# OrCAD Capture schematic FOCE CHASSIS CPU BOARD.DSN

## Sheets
1 PIC: size C; title: FOCE Chassis CPU Board; rev: A
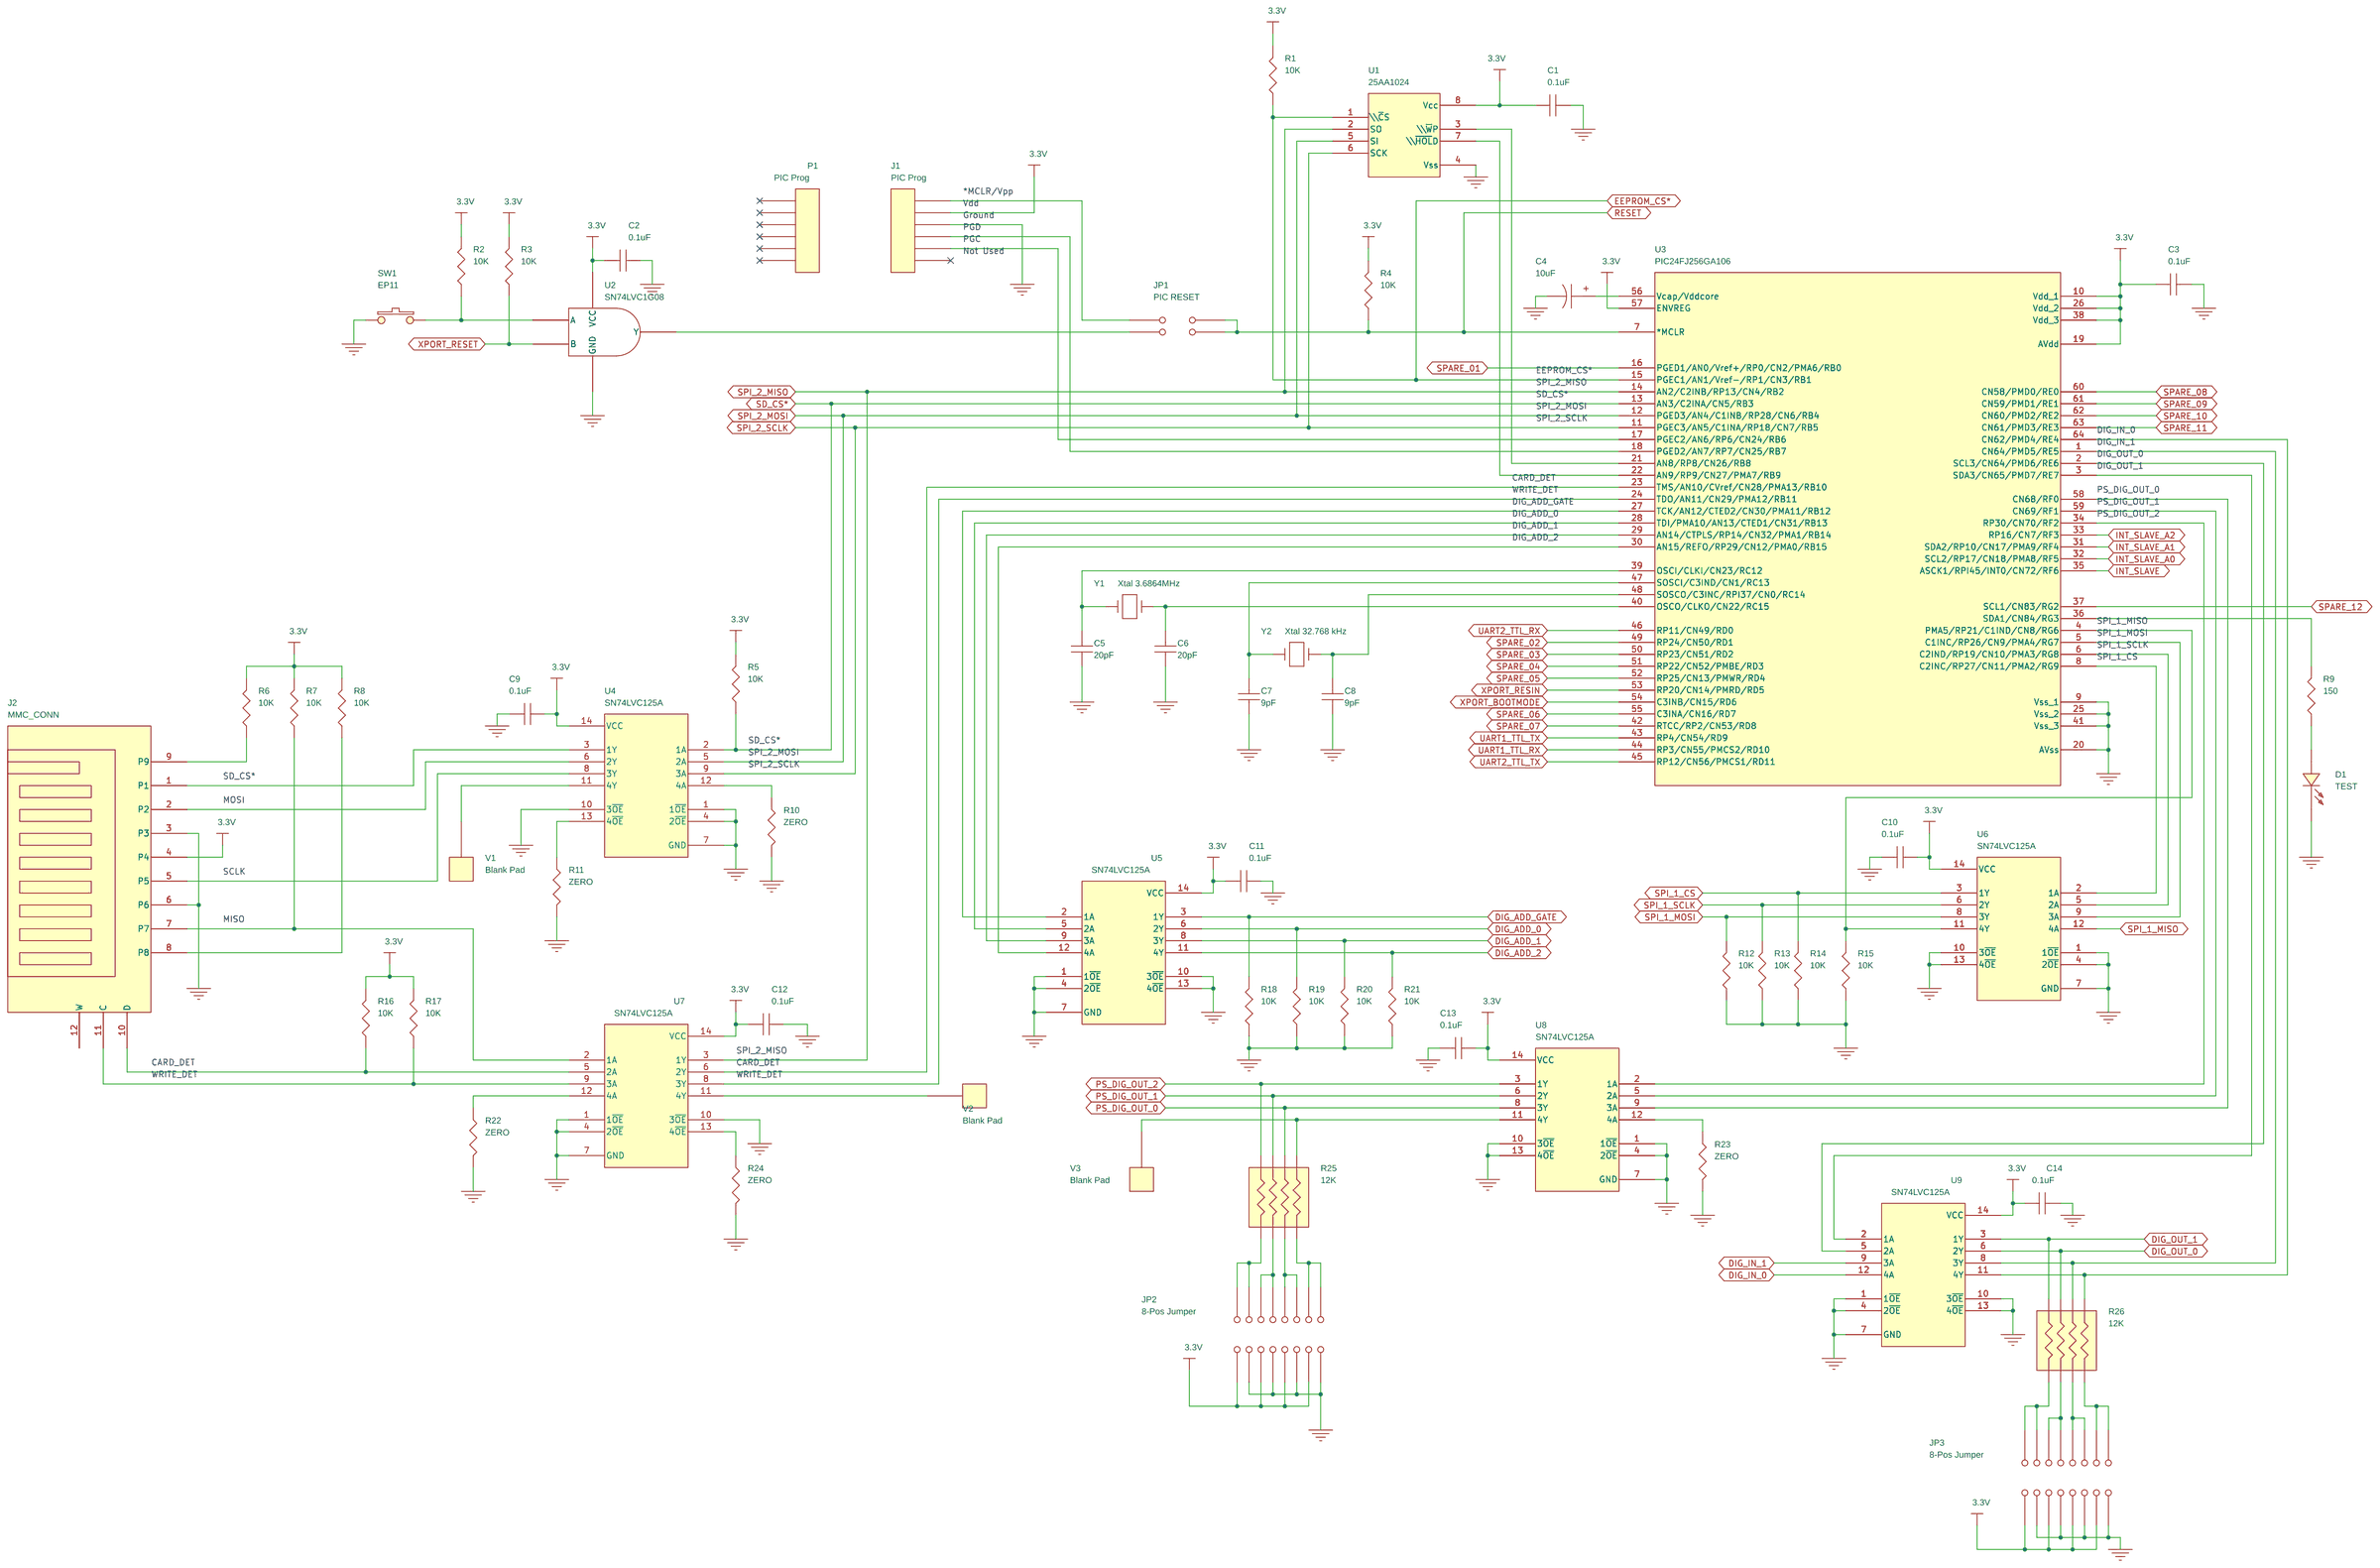
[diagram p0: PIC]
2 Backplance Connection: size C
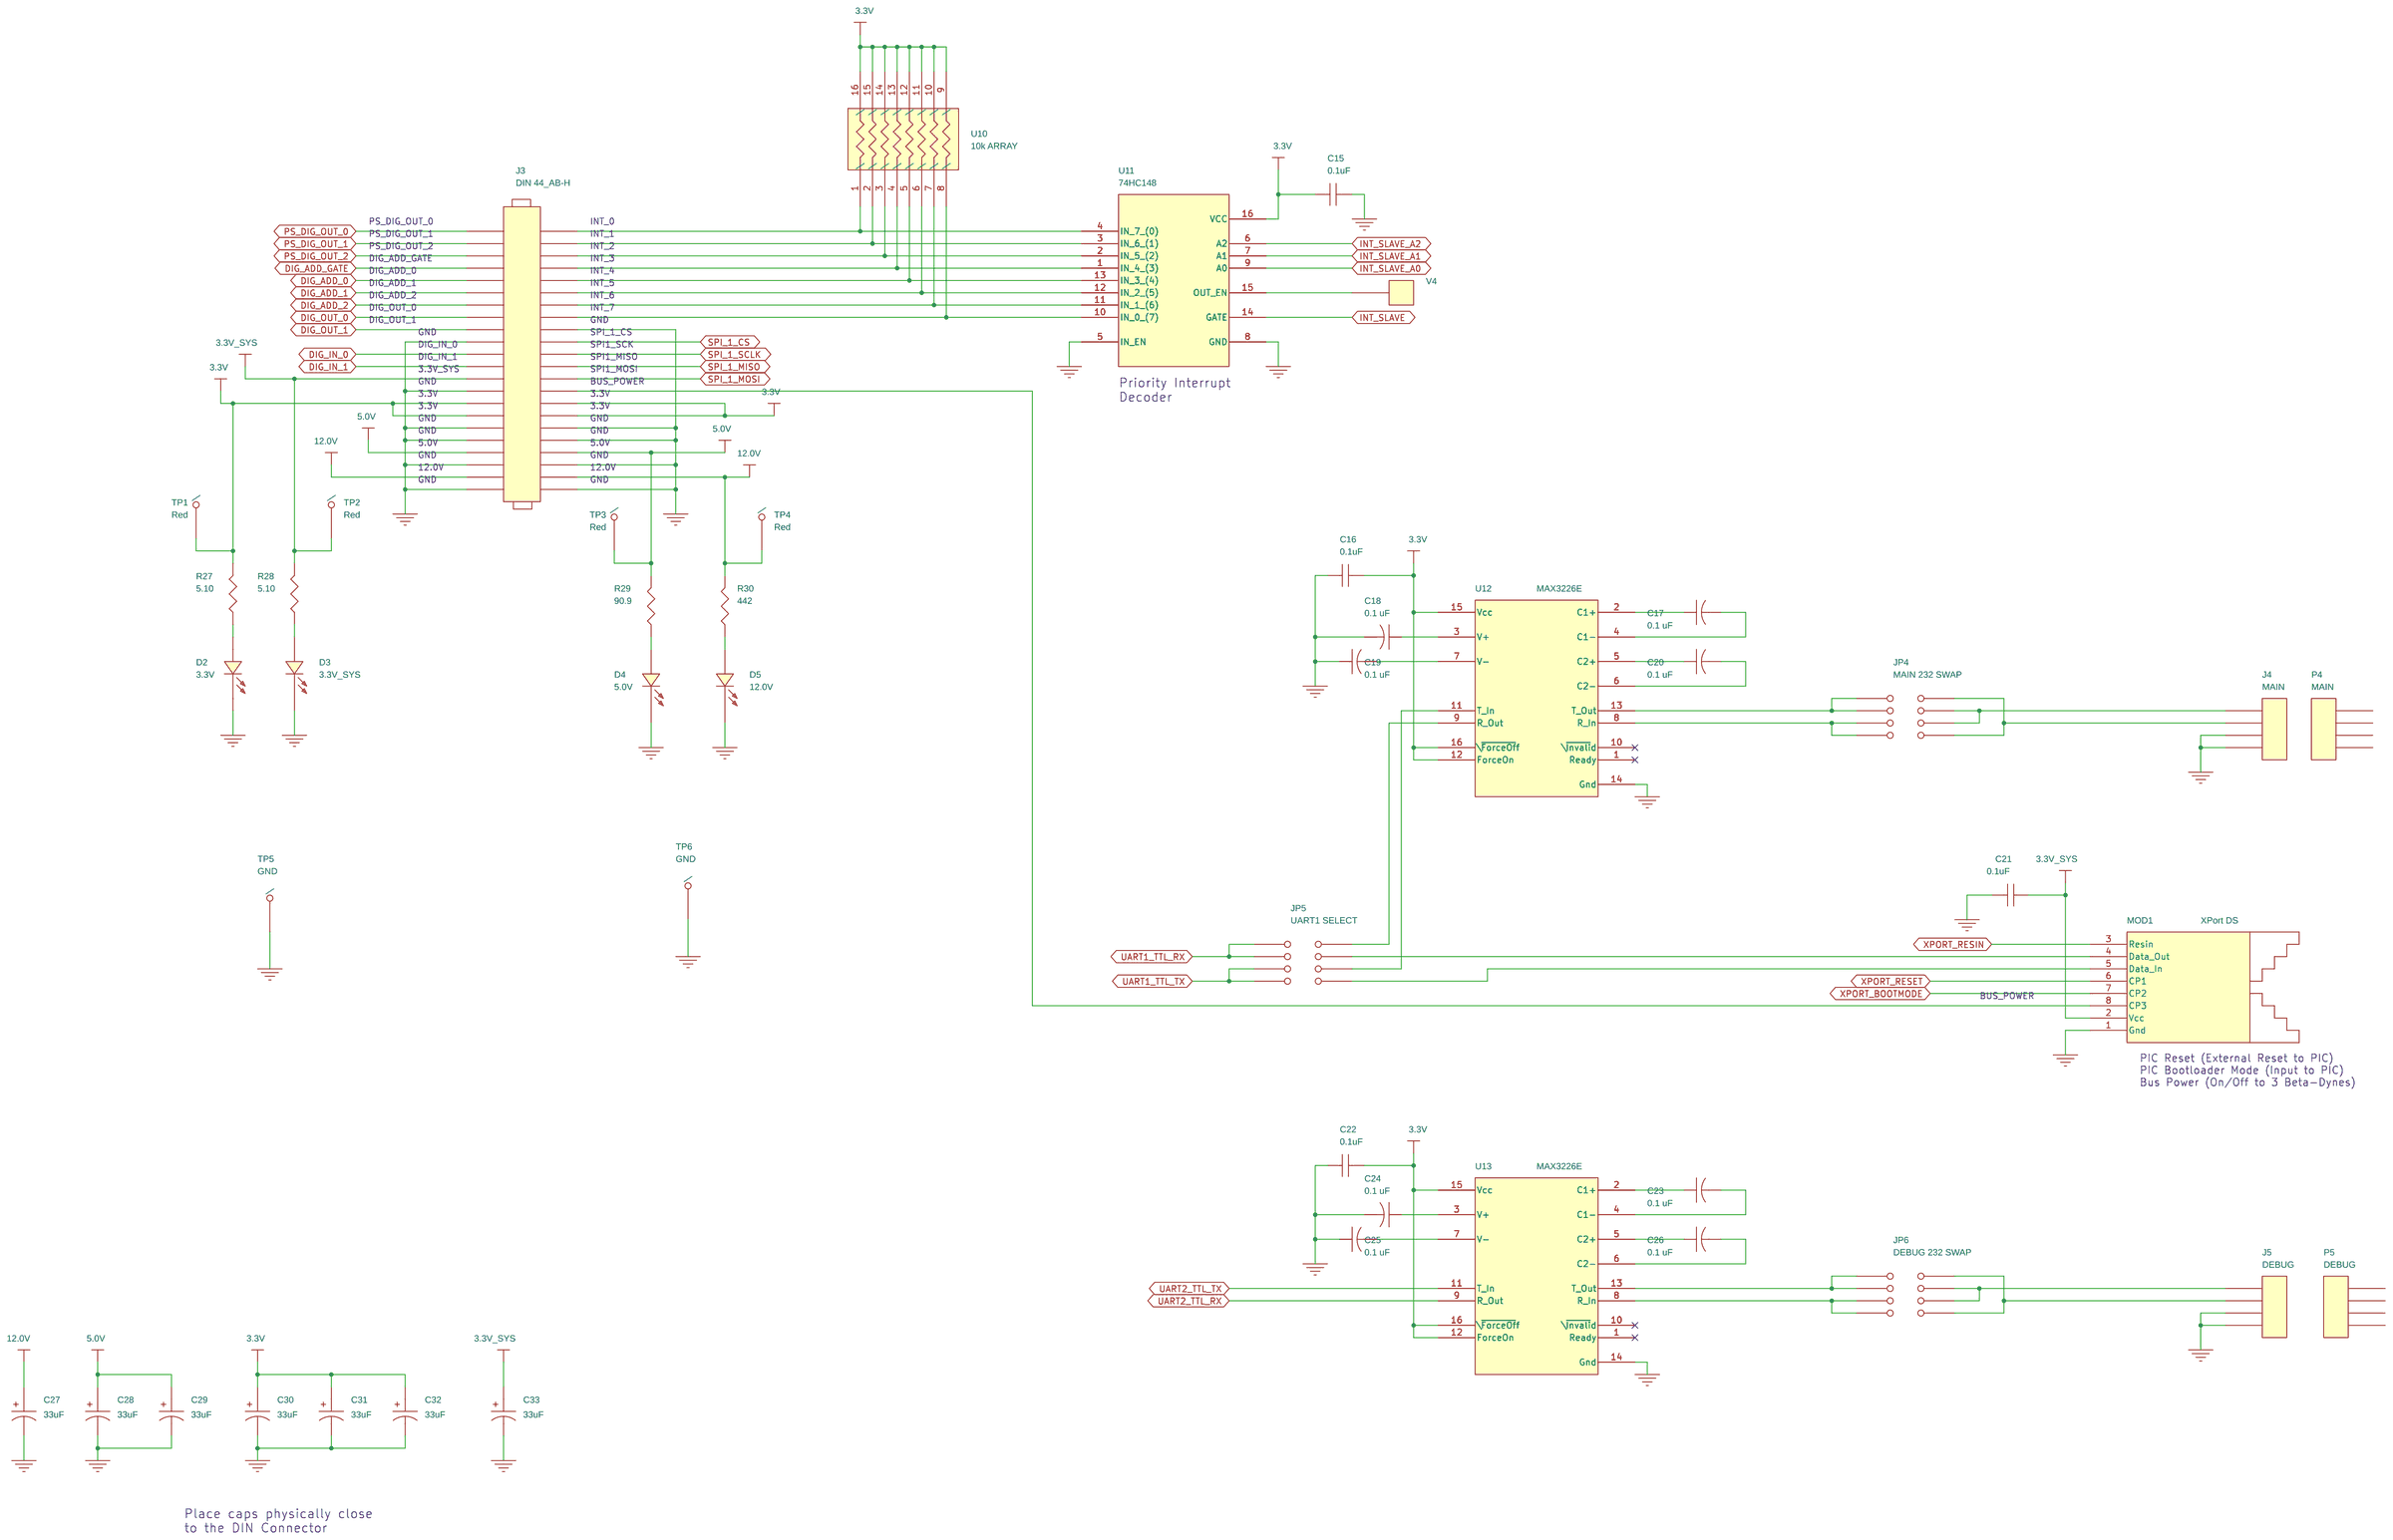
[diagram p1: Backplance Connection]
3 Test Connector: size C
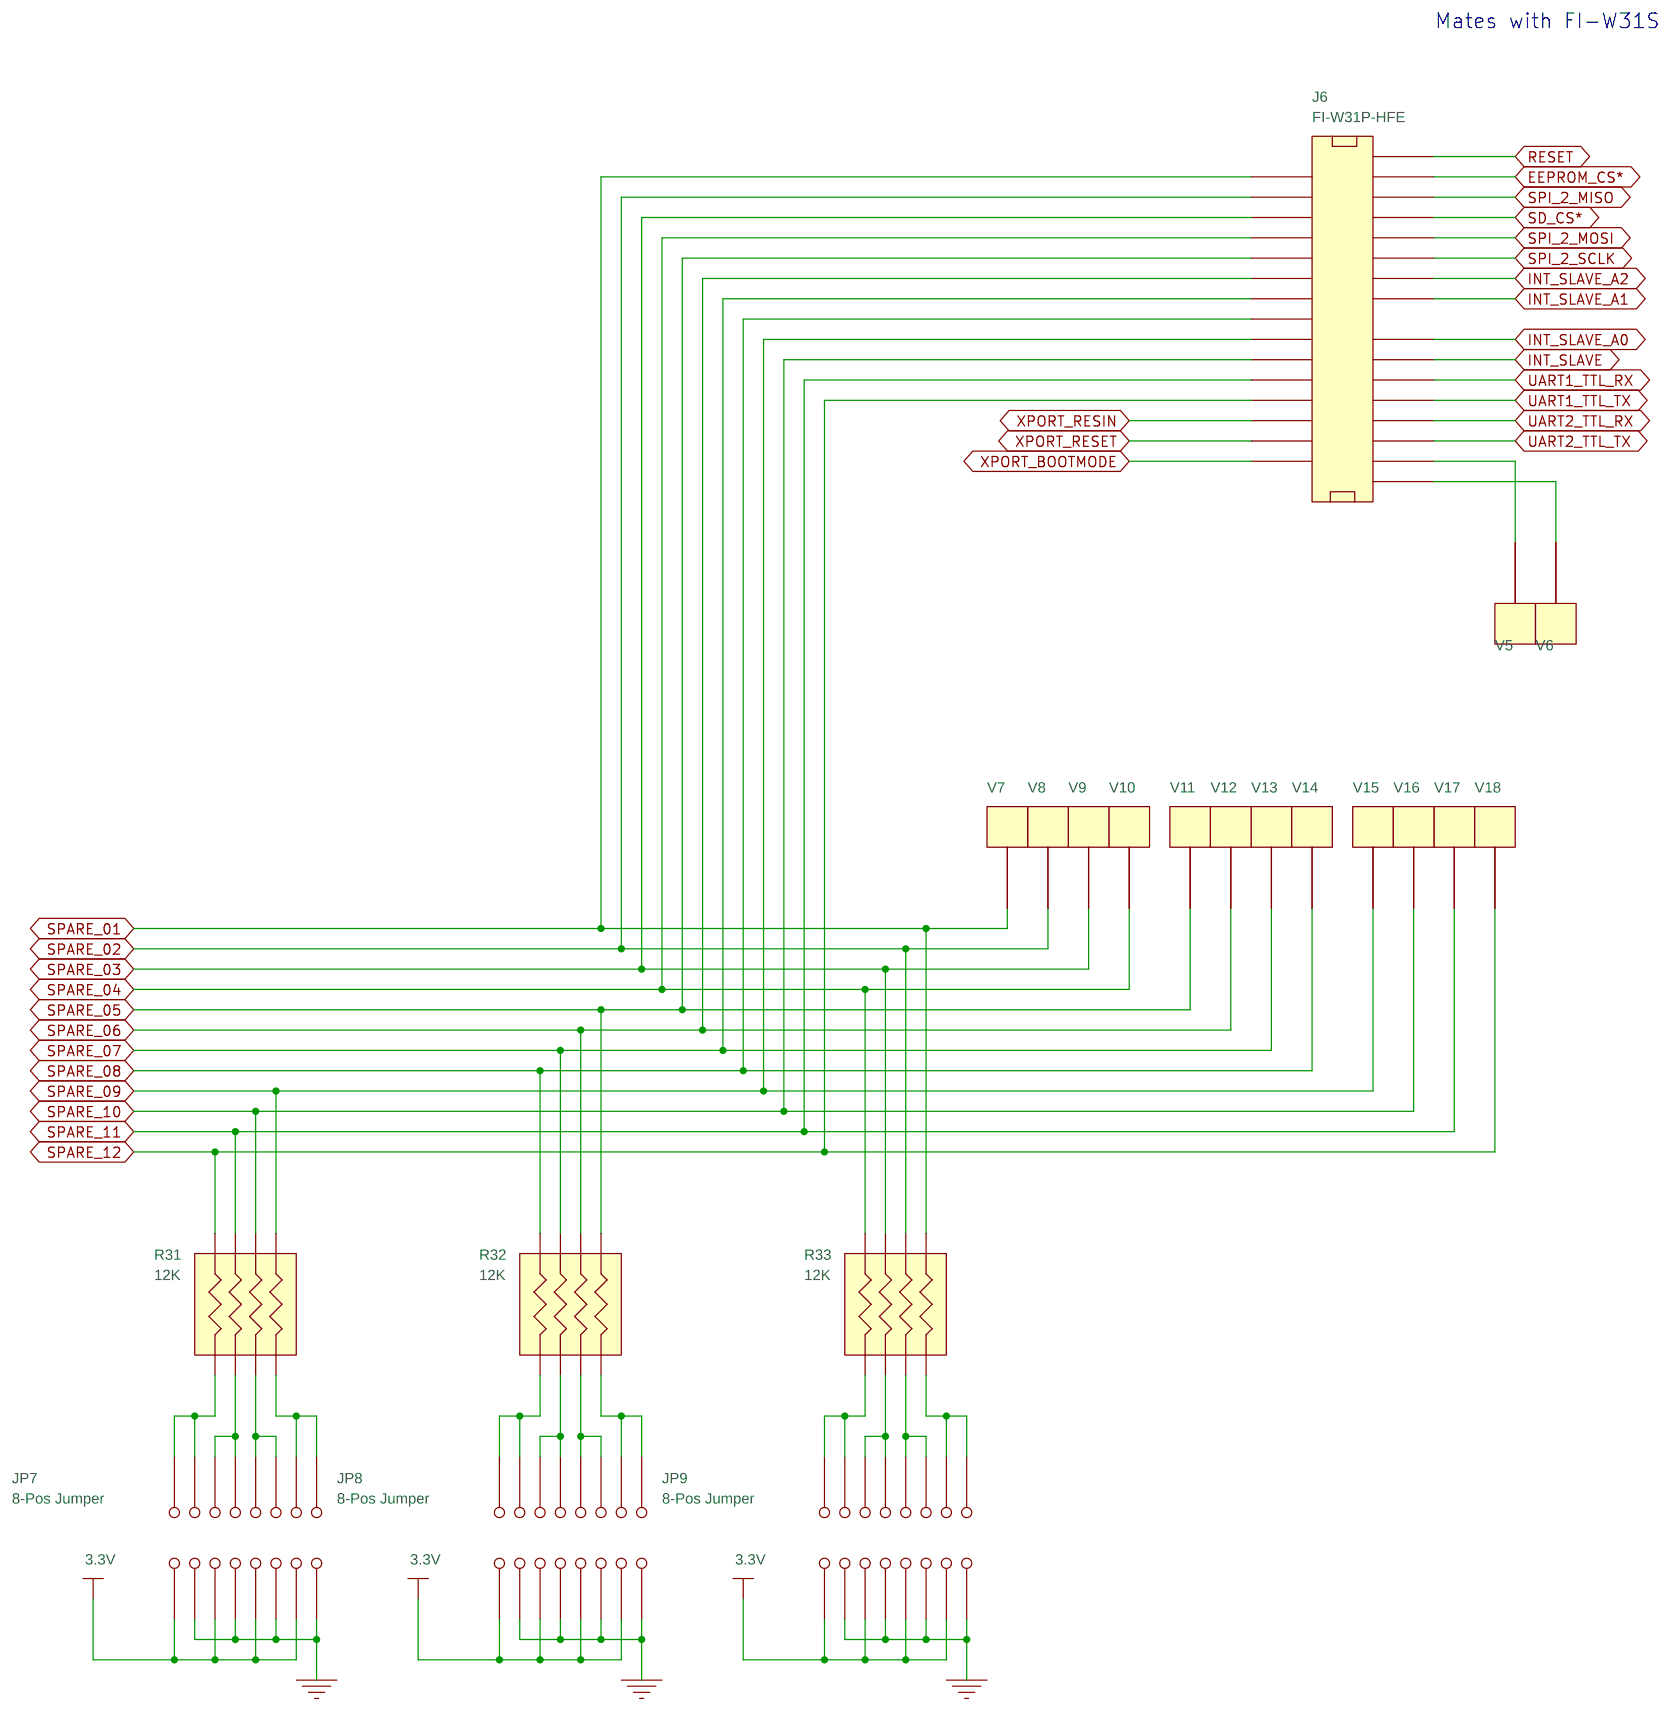
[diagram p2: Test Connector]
4 Mech Layout
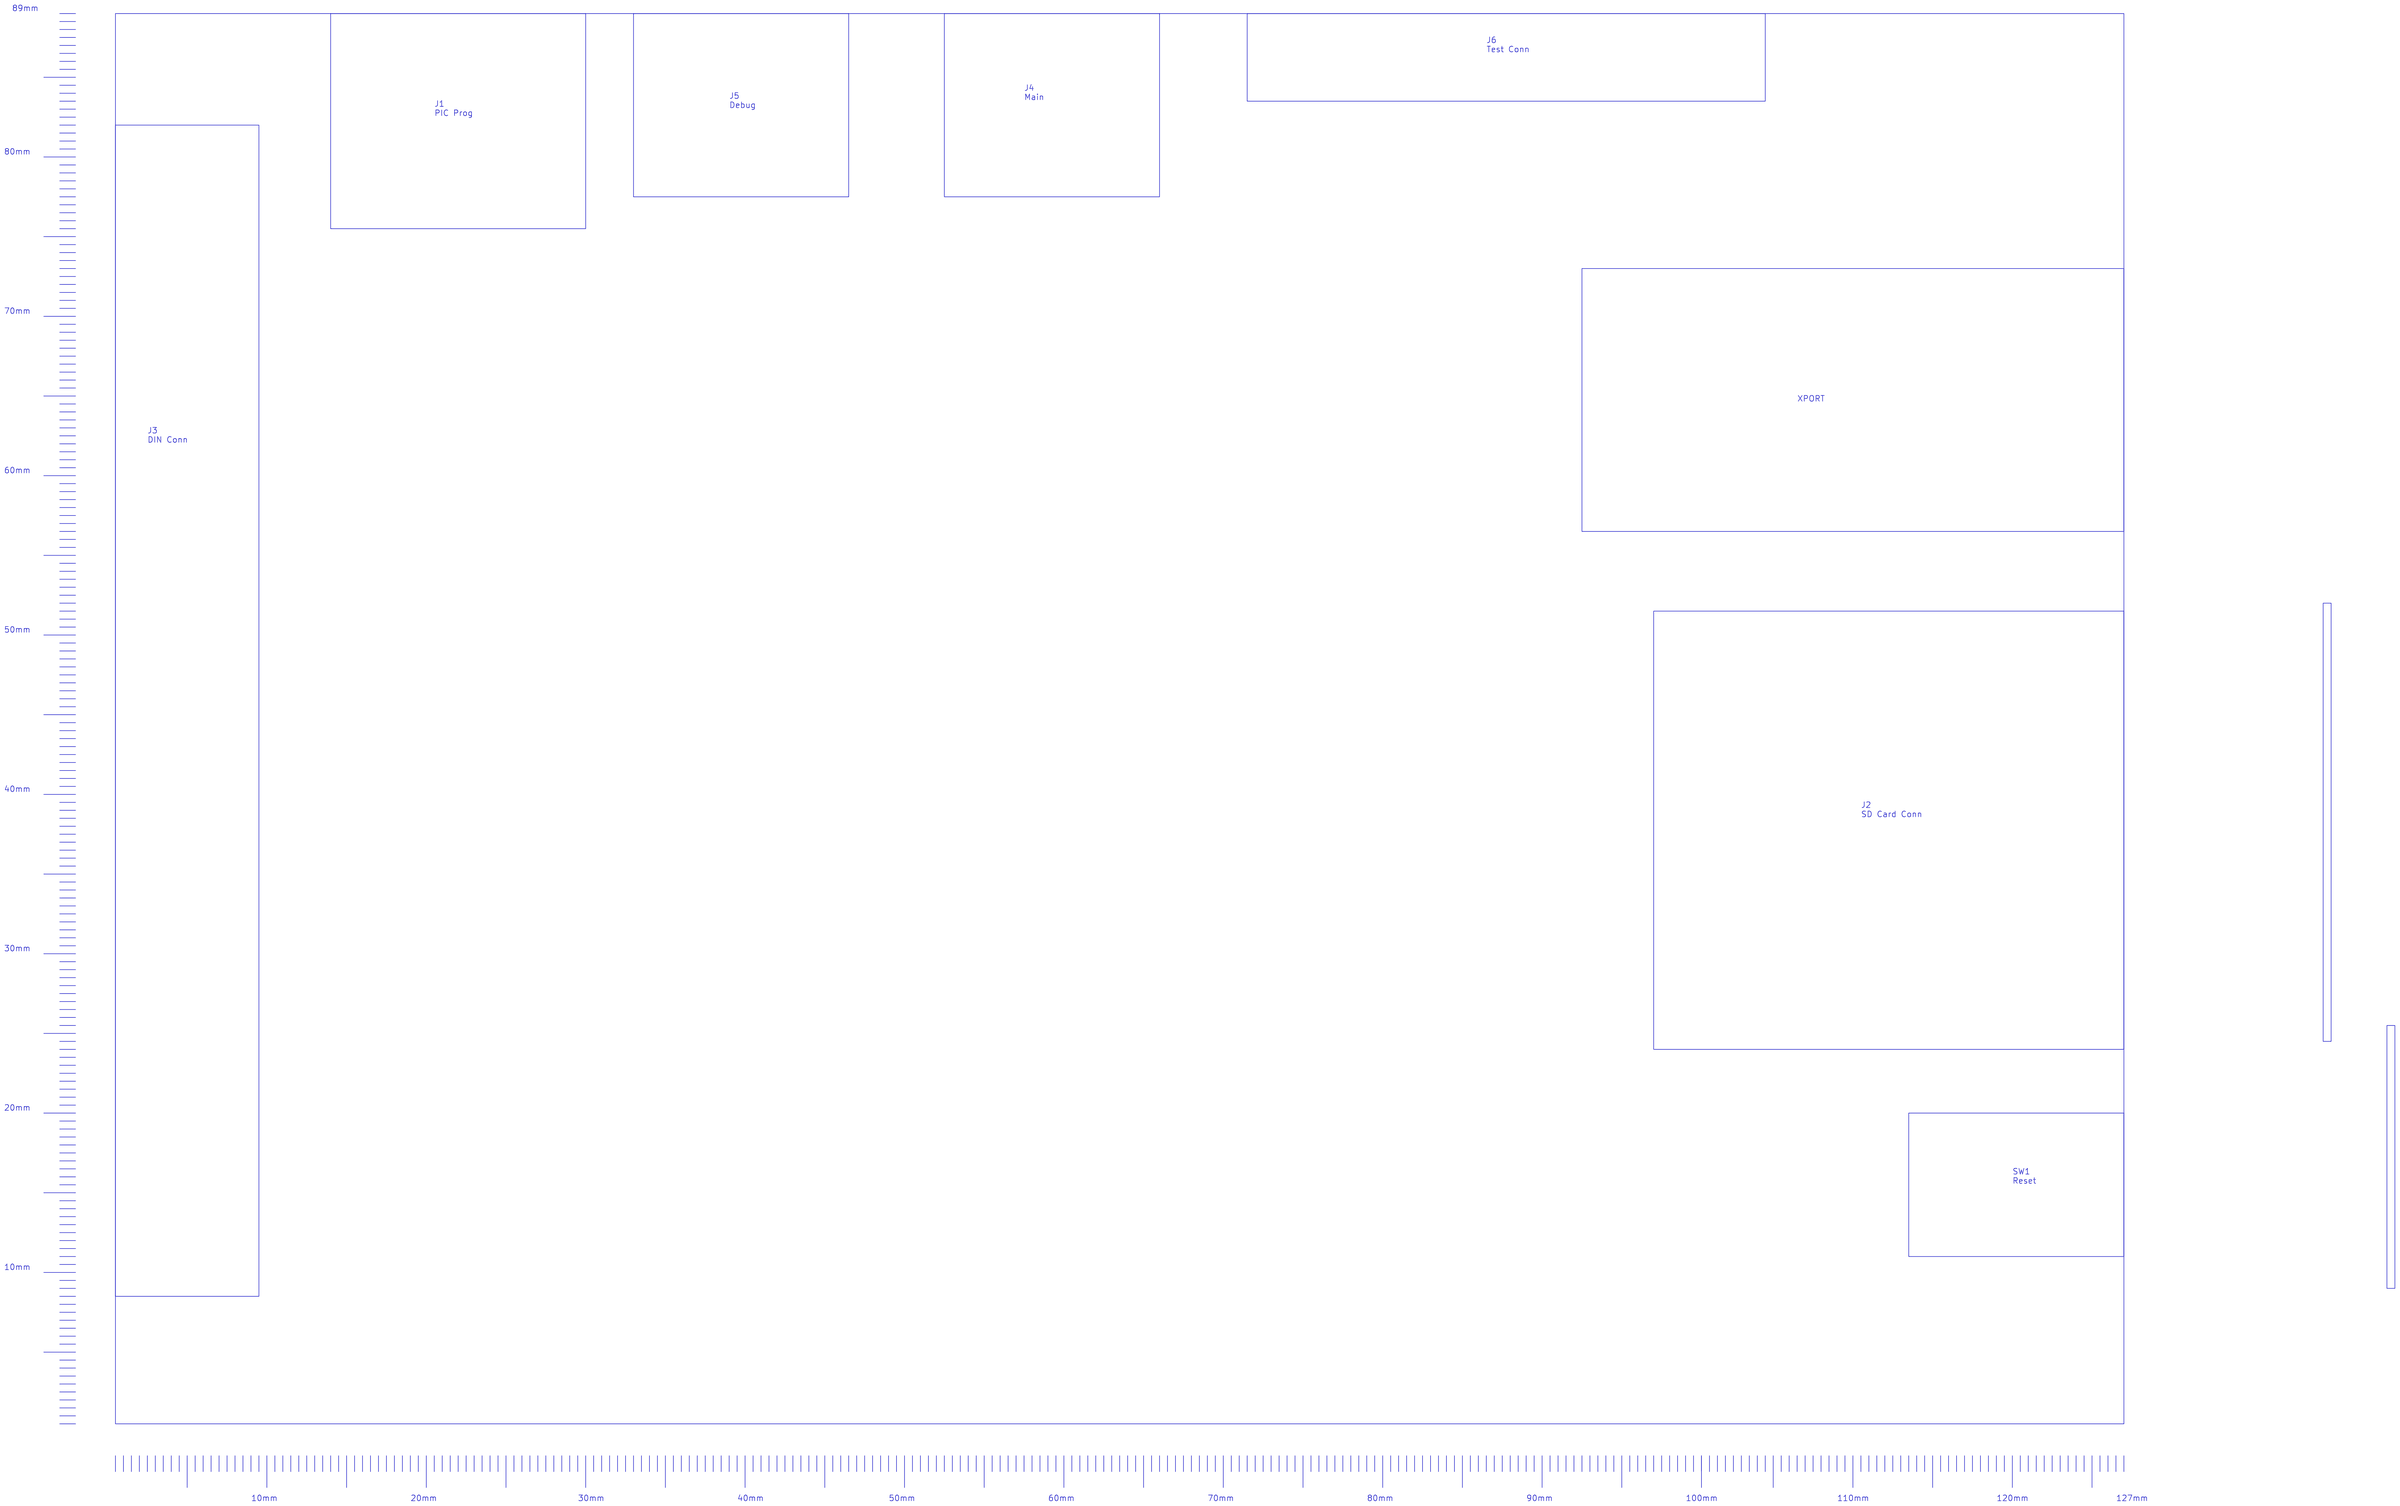
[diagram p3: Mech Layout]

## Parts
sheet Backplance Connection
C15  0.1uF  [CAPC3216X150N_1206]
C16  0.1uF  [CAPC3216X150N_1206]
C17  0.1 uF  [CAPMP3216X180N]
C18  0.1 uF  [CAPMP3216X180N]
C19  0.1 uF  [CAPMP3216X180N]
C20  0.1 uF  [CAPMP3216X180N]
C21  0.1uF  [CAPC3216X150N_1206]
C22  0.1uF  [CAPC3216X150N_1206]
C23  0.1 uF  [CAPMP3216X180N]
C24  0.1 uF  [CAPMP3216X180N]
C25  0.1 uF  [CAPMP3216X180N]
C26  0.1 uF  [CAPMP3216X180N]
C27  33uF  [CAPMP7343X430N]
C28  33uF  [CAPMP3528X210N]
C29  33uF  [CAPMP3528X210N]
C30  33uF  [CAPMP3528X210N]
C31  33uF  [CAPMP3528X210N]
C32  33uF  [CAPMP3528X210N]
C33  33uF  [CAPMP3528X210N]
D2  3.3V  [LEDC3215X130N_1206]
D3  3.3V_SYS  [LEDC3215X130N_1206]
D4  5.0V  [LEDC3215X130N_1206]
D5  12.0V  [LEDC3215X130N_1206]
J3  DIN 44_AB-H
J4  MAIN  [MOLEX_70543-0003]
J5  DEBUG  [MOLEX_70543-0003]
JP4  MAIN 232 SWAP
JP5  UART1 SELECT
JP6  DEBUG 232 SWAP
MOD1  XPort DS
P4  MAIN  [DUMMY]
P5  DEBUG  [DUMMY]
R27  5.10  [RESC3216X60N_1206]
R28  5.10  [RESC3216X60N_1206]
R29  90.9  [RESC3216X60N_1206]
R30  442  [RESC3216X60N_1206]
TP1  Test Point  [TP_5005-5009_5120-5124]
TP2  Test Point  [TP_5005-5009_5120-5124]
TP3  Test Point  [TP_5005-5009_5120-5124]
TP4  Test Point  [TP_5005-5009_5120-5124]
TP5  Test Point  [TP_5005-5009_5120-5124]
TP6  Test Point  [TP_5005-5009_5120-5124]
U10  10k ARRAY  [SOIC127P600X175-16N_SOIC16]
U11  74HC148  [SOIC127P600X175-16N_SOIC16]
U12  MAX3226E  [SOP65P778X199-16N_SSOP16]
U13  MAX3226E  [SOP65P778X199-16N_SSOP16]
V4  Blank Pad  [MISC_SM-TP]
sheet PIC
C1  0.1uF  [CAPC3216X150N_1206]
C2  0.1uF  [CAPC3216X150N_1206]
C3  0.1uF  [CAPC3216X150N_1206]
C4  10uF  [CAPMP3528X210N]
C5  20pF  [CAPC3216X150N_1206]
C6  20pF  [CAPC3216X150N_1206]
C7  9pF  [RESC1608X55N_0603]
C8  9pF  [RESC1608X55N_0603]
C9  0.1uF  [CAPC3216X150N_1206]
C10  0.1uF  [CAPC3216X150N_1206]
C11  0.1uF  [CAPC3216X150N_1206]
C12  0.1uF  [CAPC3216X150N_1206]
C13  0.1uF  [CAPC3216X150N_1206]
C14  0.1uF  [CAPC3216X150N_1206]
D1  TEST  [LEDC2013X110N_0805]
J1  PIC Prog
J2  MMC_CONN
JP1  2-Pos Jumper
JP2  8-Pos Jumper
JP3  8-Pos Jumper
P1  PIC Prog  [DUMMY]
R1  10K  [RESC3216X60N_1206]
R2  10K  [RESC3216X60N_1206]
R3  10K  [RESC3216X60N_1206]
R4  10K  [RESC3216X60N_1206]
R5  10K  [RESC3216X60N_1206]
R6  10K  [RESC3216X60N_1206]
R7  10K  [RESC3216X60N_1206]
R8  10K  [RESC3216X60N_1206]
R9  150  [RESC3216X60N_1206]
R10  ZERO  [RESC3216X60N_1206]
R11  ZERO  [RESC3216X60N_1206]
R12  10K  [RESC3216X60N_1206]
R13  10K  [RESC3216X60N_1206]
R14  10K  [RESC3216X60N_1206]
R15  10K  [RESC3216X60N_1206]
R16  10K  [RESC3216X60N_1206]
R17  10K  [RESC3216X60N_1206]
R18  10K  [RESC3216X60N_1206]
R19  10K  [RESC3216X60N_1206]
R20  10K  [RESC3216X60N_1206]
R21  10K  [RESC3216X60N_1206]
R22  ZERO  [RESC3216X60N_1206]
R23  ZERO  [RESC3216X60N_1206]
R24  ZERO  [RESC3216X60N_1206]
R25  12K
R26  12K
SW1  EP11  [SW_EP11FPD1APE]
U1  25AA1024
U2  SN74LVC1G08  [SOT95P280X145-5N_DBV]
U3  PIC24FJ256GA106  [QFP50P1200X1200X160-64N]
U4  SN74LVC125A  [SOIC127P600X175-14N_SOIC14]
U5  SN74LVC125A  [SOIC127P600X175-14N_SOIC14]
U6  SN74LVC125A  [SOIC127P600X175-14N_SOIC14]
U7  SN74LVC125A  [SOIC127P600X175-14N_SOIC14]
U8  SN74LVC125A  [SOIC127P600X175-14N_SOIC14]
U9  SN74LVC125A  [SOIC127P600X175-14N_SOIC14]
V1  Blank Pad  [MISC_SM-TP]
V2  Blank Pad  [MISC_SM-TP]
V3  Blank Pad  [MISC_SM-TP]
Y1  Xtal 3.6864MHz  [XTAL1140X470X430N_ECS-CSM-7]
Y2  Xtal 32.768 kHz
sheet Test Connector
J6  FI-W31P-HFE
JP7  8-Pos Jumper
JP8  8-Pos Jumper
JP9  8-Pos Jumper
R31  12K
R32  12K
R33  12K
V5  Blank Pad
V6  Blank Pad
V7  Blank Pad
V8  Blank Pad
V9  Blank Pad
V10  Blank Pad
V11  Blank Pad
V12  Blank Pad
V13  Blank Pad
V14  Blank Pad
V15  Blank Pad
V16  Blank Pad
V17  Blank Pad
V18  Blank Pad

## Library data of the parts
C11 C15 = Cap_Cer_0.1uF_1: ECJ Ceramic 10% 0.1uF 16V; Manuf PN: ECJ-3VB1C104K; Manufacturer: Panasonic-ECG; PACKAGE: 1206; Supplier: Digikey; Supplier PN: PCC1870CT-ND
C16 C22 = Cap_Cer_0_0.1uF: X7R 10% 25V 0.1uF; Manuf PN: ECJ-3VB1E104K; Manufacturer: Panasonic-ECG; Package: 1206; Supplier: Digikey; Supplier PN: PCC1883CT-ND
C17-C20 C23-C26 = CAP: Tant 10% 35V 0.1uF; Manuf PN: TAJA104K035R; Manufacturer: AVX Corp; Package: 3216-18; Supplier: Digikey; Supplier PN: 478-2368-1-ND
C21 = Cap_Cer_0.1uF: ECJ Ceramic 10% 0.1uF 16V; Manuf PN: ECJ-3VB1C104K; Manufacturer: Panasonic-ECG; PACKAGE: 1206; Supplier: Digikey; Supplier PN: PCC1870CT-ND
C27 = Cap_Tant_10uF: 33uF 20V 20% TPS Tantulum; Manuf PN: TPSD336M020RO200; Manufacturer: AVX Corp; Package: 7343-31 (EIA); Supplier: Digikey; Supplier PN: 478-4111-1-ND
C28 = Cap_Tant_10uF_1: 33uF 10V 20% TCJ Tantulum; Manuf PN: TCJB336M010R0070; Manufacturer: AVX Corp; Package: 3528-21 (EIA); Supplier: Digikey; Supplier PN: 478-4713-1-ND
C29 = Cap_Tant_10uF_2: 33uF 10V 20% TCJ Tantulum; Manuf PN: TCJB336M010R0070; Manufacturer: AVX Corp; Package: 3528-21 (EIA); Supplier: Digikey; Supplier PN: 478-4713-1-ND
C30 = Cap_Tant_10uF_3: 33uF 10V 20% TCJ Tantulum; Manuf PN: TCJB336M010R0070; Manufacturer: AVX Corp; Package: 3528-21 (EIA); Supplier: Digikey; Supplier PN: 478-4713-1-ND
C31 = Cap_Tant_10uF_5: 33uF 10V 20% TCJ Tantulum; Manuf PN: TCJB336M010R0070; Manufacturer: AVX Corp; Package: 3528-21 (EIA); Supplier: Digikey; Supplier PN: 478-4713-1-ND
C32 = Cap_Tant_10uF_6: 33uF 10V 20% TCJ Tantulum; Manuf PN: TCJB336M010R0070; Manufacturer: AVX Corp; Package: 3528-21 (EIA); Supplier: Digikey; Supplier PN: 478-4713-1-ND
C33 = Cap_Tant_10uF_4: 33uF 10V 20% TCJ Tantulum; Manuf PN: TCJB336M010R0070; Manufacturer: AVX Corp; Package: 3528-21 (EIA); Supplier: Digikey; Supplier PN: 478-4713-1-ND
D2-D5 = LED: Green Clear; Manuf PN: 598-8281-107F; Manufacturer: Dialight; Package: 1206; Supplier: Digikey; Supplier PN: 350-2054-1-ND
J3 = DIN_44_AB-H_0: Female Right Angle 44-pin DIN; Manuf PN: PCN10C-44S-2.54DS(72); Manufacturer: Hirose; Supplier: Digikey; Supplier PN: H11171-ND
J4 J5 = CON4: 4-Pin Male Header RA; Manuf PN: 70543-0108; Manufacturer: Molex/Waldom; Package: Thru-Hole RA; Supplier: Digikey; Supplier PN: WM4155-ND
JP4-JP6 = 4-Pos_Jumper_0: 8-Pos (2x4) Male header 2mm pitch; Manuf PN: 151208-8421-RB; Manufacturer: 3M; Package: Thru-Hole; Supplier: Digikey; Supplier PN: 3M5353-ND
MOD1 = XPort_DS_0: Ser-Eth Module; Manuf PN: XP1001000-04R; Manufacturer: Lantronix; Package: Module; Supplier: Mouser; Supplier PN: 515-XP1001000-04R
P4 P5 = CON4: 4-Pin Female Recp Plug; Manuf PN: 50-57-9404; Manufacturer: Molex; Package: Free Hanging; Supplier: Digikey; Supplier PN: WM2902-ND
R27 R28 = RESISTOR: 5.1ohm 0.25W ERJ; Manuf PN: ERJ-8GEYJ5R1V; Manufacturer: Panasonic-ECG; Package: 1206; Supplier: Digikey; Supplier PN: P5.1ECT-ND
R29 = RESISTOR: ERJ 0.25W 90.9 1%; Manuf PN: ERJ-8ENF90R9V; Manufacturer: Panasonic-ECG; Package: 1206; Supplier: Digikey; Supplier PN: P90.9FCT-ND
R30 = RESISTOR: ERJ 0.25W 442 1%; Manuf PN: ERJ-8ENF4420V; Manufacturer: Panasonic-ECG; Package: 1206; Supplier: Digikey; Supplier PN: P442FCT-ND
TP1-TP4 = Test_Point: Compact Series Red; Manuf PN: 5005; Manufacturer: Keystone; Package: 0.063" Thru-Hole; Part Name: Red; Supplier: Digikey; Supplier PN: 5005K-ND
TP5 TP6 = Test_Point: Compact Series Black; Manuf PN: 5006; Manufacturer: Keystone; Package: 0.063" Thru-Hole; Part Name: GND; Supplier: Digikey; Supplier PN: 5006K-ND
U10 = 100K_x8_Res_Array: 10Kx8 Resistors; Manuf PN: NOMCT16031002AT1; Manufacturer: Vishay; Package: 16-SOIC; Supplier: Digikey; Supplier PN: NOMCT16-10KACT-ND
U11 = 74HC148_1: 1x8:3 Priority Encoder; Manuf PN: SN74HC148D; Manufacturer: Texas Instruments; Package: 16-SOIC; Supplier: Digikey; Supplier PN: 296-8232-5-ND
U12 U13 = MAX3226E_1: RS 232 Xcvr; Manuf PN: MAX3226ECAE+; Manufacturer: Maxim IC; Package: 16-SSOP; Supplier: Digikey; Supplier PN: MAX3226ECAE+-ND
V1-V4 = Blank_Pad
C1 = Cap_Cer_0.1uF_8: ECJ Ceramic 10% 0.1uF 16V; Manuf PN: ECJ-3VB1C104K; Manufacturer: Panasonic-ECG; PACKAGE: 1206; Supplier: Digikey; Supplier PN: PCC1870CT-ND
C2 = Cap_Cer_0.1uF_9: ECJ Ceramic 10% 0.1uF 16V; Manuf PN: ECJ-3VB1C104K; Manufacturer: Panasonic-ECG; PACKAGE: 1206; Supplier: Digikey; Supplier PN: PCC1870CT-ND
C3 = Cap_Cer_0.1uF_5: ECJ Ceramic 10% 0.1uF 16V; Manuf PN: ECJ-3VB1C104K; Manufacturer: Panasonic-ECG; PACKAGE: 1206; Supplier: Digikey; Supplier PN: PCC1870CT-ND
C4 = CAPACITOR_POL: 10uF 16V 10%; Manuf PN: TAJB106K016RNJ; Manufacturer: AVX Corp; Package: 3528-21; Supplier: Digikey; Supplier PN: 478-1673-1-ND
C5 = Cap_Cer_0.1uF: CC Cer 5% COG 20pF 50V; Manuf PN: CC1206JRNP09BN200; Manufacturer: Yageo; Package: 1206; Supplier: Digikey; Supplier PN: 311-1153-1-ND
C6 = Cap_Cer_0.1uF_3: CC Cer 5% COG 20pF 50V; Manuf PN: CC1206JRNP09BN200; Manufacturer: Yageo; Package: 1206; Supplier: Digikey; Supplier PN: 311-1153-1-ND
C7 C8 = Cap_Cer_0_0.1uF: Cer COG 0.25pF 50V GQM; GROUP: 1; Manuf PN: GQM1885C1H9R0CB01D; Manufacturer: Murata; Package: 0603; Supplier: Digikey; Supplier PN: 490-3568-1-ND
C9 = Cap_Cer_0.1uF_10: ECJ Ceramic 10% 0.1uF 16V; Manuf PN: ECJ-3VB1C104K; Manufacturer: Panasonic-ECG; PACKAGE: 1206; Supplier: Digikey; Supplier PN: PCC1870CT-ND
C10 = Cap_Cer_0.1uF_2: ECJ Ceramic 10% 0.1uF 16V; Manuf PN: ECJ-3VB1C104K; Manufacturer: Panasonic-ECG; PACKAGE: 1206; Supplier: Digikey; Supplier PN: PCC1870CT-ND
C12 = Cap_Cer_0.1uF_4: ECJ Ceramic 10% 0.1uF 16V; Manuf PN: ECJ-3VB1C104K; Manufacturer: Panasonic-ECG; PACKAGE: 1206; Supplier: Digikey; Supplier PN: PCC1870CT-ND
C13 = Cap_Cer_0.1uF_6: ECJ Ceramic 10% 0.1uF 16V; Manuf PN: ECJ-3VB1C104K; Manufacturer: Panasonic-ECG; PACKAGE: 1206; Supplier: Digikey; Supplier PN: PCC1870CT-ND
C14 = Cap_Cer_0.1uF_7: ECJ Ceramic 10% 0.1uF 16V; Manuf PN: ECJ-3VB1C104K; Manufacturer: Panasonic-ECG; PACKAGE: 1206; Supplier: Digikey; Supplier PN: PCC1870CT-ND
D1 = LED: Green; Manuf PN: LP M67K-E2G1-25-Z; Manufacturer: Osram; Package: 0805; Supplier: Digikey; Supplier PN: 475-2750-1-ND
J1 = CONN_TRBLK_6: 6-Pos RA Male Header; Manuf PN: 70553-0110; Manufacturer: Molex; Package: Thru-Hole RA; Supplier: Digikey; Supplier PN: WM4157-ND
J2 = MMC_Conn: MMC-SD RA Connector; Manuf PN: 101-00405-75; Manufacturer: Amphenol; Package: Surface Mount; Supplier: Digikey; Supplier PN: 101-00405-75-ND
JP1 = 2-Pos_Jumper_0: 4-Pos (2x2) Male header 2mm pitch; Manuf PN: 151204-2320-RB; Manufacturer: 3M; Package: SMD; Part Name: PIC RESET; Supplier: Digikey; Supplier PN: 3M5350-ND
JP2 JP3 JP7-JP9 = 8-Pos_Jumper: 16 Pos (2x8) Male Header 2mm pitch; Manuf PN: 151216-8422-RB; Manufacturer: 3M; Package: Thru Hole; Supplier: Digikey; Supplier PN: 3M5362-ND
P1 = CONN_TRBLK_6: 6-Pos Female Recp Plug; Manuf PN: 50-57-9406; Manufacturer: Molex; Package: Free Hanging; Supplier: Digikey; Supplier PN: WM2904-ND
R1-R8 R12-R21 = RESISTOR: ERJ 0.25W 10K 1%; Manuf PN: ERJ-8ENF1002V; Manufacturer: Panasonic-ECG; Package: 1206; Supplier: Digikey; Supplier PN: P10.0KFCT-ND
R9 = RESISTOR: ERJ 0.25W 150 1%; Manuf PN: ERJ-8ENF1500V; Manufacturer: Panasonic-ECG; Package: 1206; Supplier: Digikey; Supplier PN: P150FCT-ND
R10 R11 R22-R24 = RESISTOR: ERJ 0.25W 5%; Manuf PN: P0.0ECT-ND; Manufacturer: Panasonic-ECG; Package: 1206; Supplier: Digikey; Supplier PN: ERJ-8GEY0R0-V
R25 R26 R31-R33 = 744C083_0: 12.0K 200ppm 5% Quad Array; Manuf PN: 744C083123JPTR; Manufacturer: CTS Resistor; Package: 1206 x 4; Supplier: Digikey; Supplier PN: 744C083123JPCT-ND
SW1 = Swtich_SPST-NO: SPST-NO Off-Mom; Manuf PN: EP11FPD1APE; Manufacturer: C&K Components; Package: Through Hole; Supplier: Digikey; Supplier PN: CKN9129-ND
U1 = 25AA1024: 1M SPI-EEPROM; Manuf PN: 25AA1024-I/SM; Manufacturer: Microchip Technology; Package: 8-SOICJ; Supplier: Digikey; Supplier PN: 25AA1024-I/SM-ND
U2 = 74LVC1G08: Single Gate 2-in AND Gate; Manuf PN: SN74LVC1G08DBVR; Manufacturer: Texas Instruments; Package: SOT23-5; Supplier: Digikey; Supplier PN: 296-11601-1-ND
U3 = PIC24FJ256GA106_3: 16-Bit 64-Pin PIC uC; Manuf PN: PIC24FJ256GA106-I/PT; Manufacturer: Microchip Technology; Package: 64-TQFP; Supplier: Digikey; Supplier PN: PIC24FJ256GA106-I/PT-ND
U4-U9 = SN74LVC125A: Quad Tri-State Buffer; Manuf PN: SN74LVC125ADR; Manufacturer: Texas Instruments; Package: 14-SOIC; Supplier: Digikey; Supplier PN: 296-8453-1-ND
Y1 = Xtal_1.8432MHz: Quartz Xtal Fund. 30ppm; Manuf PN: ECS-36-20-5PXDU-TR; Manufacturer: ECS Inc.; Package: SMD; Supplier: Digikey; Supplier PN: XC1523CT-ND
Y2 = Xtal_1_0.8432MHz: Quartz Fund 20ppm; GROUP: 1; Manuf PN: FC-135 32.7680KA-A3; Manufacturer: Epson Toyocom; Package: SMD; Supplier: Digikey; Supplier PN: SE2413CT-ND
J6 = F1_Series_JAE_Connector: 31-Pin RA Male Header; Manufacturer: JAE Electronics; Package: Thru-Hole; Supplier: Digikey; Supplier PN: 670-1722-ND
V5-V18 = Blank_Pad: Package: MISC_SM-TP

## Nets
3.3V: C1.1 C2.2 C3.1 C9.1 C10.1 C11.2 C12.2 C13.1 C14.1 C15.1 C16.2 C22.2 C30.1 C31.1 C32.1 J1.2 J2.4(P4) J3.A15 J3.A16 J3.B15 J3.B16 JP2.3 JP2.7 JP2.11 JP2.15 JP3.3 JP3.7 JP3.11 JP3.15 JP7.3 JP7.7 JP7.11 JP7.15 JP8.3 JP8.7 JP8.11 JP8.15 JP9.3 JP9.7 JP9.11 JP9.15 R1.2 R2.2 R3.2 R4.2 R5.2 R6.2 R7.2 R8.2 R16.2 R17.2 R27.2 TP1.\ U1.8(Vcc) U2.5(VCC) U3.10(Vdd_1) U3.19(AVdd) U3.26(Vdd_2) U3.38(Vdd_3) U3.57(ENVREG) U4.14(VCC) U5.14(VCC) U6.14(VCC) U7.14(VCC) U8.14(VCC) U9.14(VCC) U10.9(\) U10.10(\) U10.11(\) U10.12(\) U10.13(\) U10.14(\) U10.15(\) U10.16(\) U11.16(VCC) U12.12(ForceOn) U12.15(Vcc) U12.16(\~{ForceOf}f) U13.12(ForceOn) U13.15(Vcc) U13.16(\~{ForceOf}f)
3.3V_SYS: C21.1 C33.1 J3.A13 MOD1.2(Vcc) R28.2 TP2.\
5.0V: C28.1 C29.1 J3.A19 J3.B19 R29.2 TP3.\
12.0V: C27.1 J3.A21 J3.B21 R30.2 TP4.\
GND: C1.2 C2.1 C3.2 C4.2 C5.1 C6.1 C7.1 C8.1 C9.2 C10.2 C11.1 C12.1 C13.2 C14.2 C15.2 C16.1 C18.2 C19.1 C21.2 C22.1 C24.2 C25.1 C27.2 C28.2 C29.2 C30.2 C31.2 C32.2 C33.2 D1.2(CATHODE) D2.2(CATHODE) D3.2(CATHODE) D4.2(CATHODE) D5.2(CATHODE) J1.3 J2.3(P3) J2.6(P6) J3.A10 J3.A14 J3.A17 J3.A18 J3.A20 J3.A22 J3.B9 J3.B17 J3.B18 J3.B20 J3.B22 J4.3 J4.4 J5.3 J5.4 JP2.1 JP2.5 JP2.9 JP2.13 JP3.1 JP3.5 JP3.9 JP3.13 JP7.1 JP7.5 JP7.9 JP7.13 JP8.1 JP8.5 JP8.9 JP8.13 JP9.1 JP9.5 JP9.9 JP9.13 MOD1.1(Gnd) R10.2 R11.2 R12.1 R13.1 R14.1 R15.1 R18.1 R19.1 R20.1 R21.1 R22.2 R23.2 R24.2 SW1.1 TP5.\ TP6.\ U1.4(Vss) U2.3(GND) U3.9(Vss_1) U3.20(AVss) U3.25(Vss_2) U3.41(Vss_3) U4.1(1~{OE}) U4.4(2~{OE}) U4.7(GND) U4.10(3~{OE}) U5.1(1~{OE}) U5.4(2~{OE}) U5.7(GND) U5.10(3~{OE}) U5.13(4~{OE}) U6.1(1~{OE}) U6.4(2~{OE}) U6.7(GND) U6.10(3~{OE}) U6.13(4~{OE}) U7.1(1~{OE}) U7.4(2~{OE}) U7.7(GND) U7.10(3~{OE}) U8.1(1~{OE}) U8.4(2~{OE}) U8.7(GND) U8.10(3~{OE}) U8.13(4~{OE}) U9.1(1~{OE}) U9.4(2~{OE}) U9.7(GND) U9.10(3~{OE}) U9.13(4~{OE}) U11.5(IN_EN) U11.8(GND) U12.14(Gnd) U13.14(Gnd)
DIG_ADD_0: J3.A5 R19.2 U5.6(2Y)
DIG_ADD_1: J3.A6 R20.2 U5.8(3Y)
DIG_ADD_2: J3.A7 R21.2 U5.11(4Y)
DIG_ADD_GATE: J3.A4 R18.2 U5.3(1Y)
DIG_IN_0: J3.A11 U9.12(4A)
DIG_IN_1: J3.A12 U9.9(3A)
DIG_OUT_0: J3.A8 R26.5 U9.6(2Y)
DIG_OUT_1: J3.A9 R26.7 U9.3(1Y)
EEPROM_CS*: J6.3 R1.1 U1.1(\\~{C}S) U3.15(PGEC1/AN1/Vref-/RP1/CN3/RB1)
INT_SLAVE: J6.19 U3.35(ASCK1/RPI45/INT0/CN72/RF6) U11.14(GATE)
INT_SLAVE_A0: J6.17 U3.32(SCL2/RP17/CN18/PMA8/RF5) U11.9(A0)
INT_SLAVE_A1: J6.15 U3.31(SDA2/RP10/CN17/PMA9/RF4) U11.7(A1)
INT_SLAVE_A2: J6.13 U3.33(RP16/CN7/RF3) U11.6(A2)
PS_DIG_OUT_0: J3.A1 R25.3 U8.8(3Y)
PS_DIG_OUT_1: J3.A2 R25.5 U8.6(2Y)
PS_DIG_OUT_2: J3.A3 R25.7 U8.3(1Y)
RESET: J6.1 JP1.2 JP1.4 R4.1 U3.7(*MCLR)
SD_CS*: J6.7 R5.1 U3.13(AN3/C2INA/CN5/RB3) U4.2(1A)
SPARE_01: J6.2 R33.1 U3.16(PGED1/AN0/Vref+/RP0/CN2/PMA6/RB0) V7.1(Conn)
SPARE_02: J6.4 R33.3 U3.49(RP24/CN50/RD1) V8.1(Conn)
SPARE_03: J6.6 R33.5 U3.50(RP23/CN51/RD2) V9.1(Conn)
SPARE_04: J6.8 R33.7 U3.51(RP22/CN52/PMBE/RD3) V10.1(Conn)
SPARE_05: J6.10 R32.1 U3.52(RP25/CN13/PMWR/RD4) V11.1(Conn)
SPARE_06: J6.12 R32.3 U3.55(C3INA/CN16/RD7) V12.1(Conn)
SPARE_07: J6.14 R32.5 U3.42(RTCC/RP2/CN53/RD8) V13.1(Conn)
SPARE_08: J6.16 R32.7 U3.60(CN58/PMD0/RE0) V14.1(Conn)
SPARE_09: J6.18 R31.1 U3.61(CN59/PMD1/RE1) V15.1(Conn)
SPARE_10: J6.20 R31.3 U3.62(CN60/PMD2/RE2) V16.1(Conn)
SPARE_11: J6.22 R31.5 U3.63(CN61/PMD3/RE3) V17.1(Conn)
SPARE_12: J6.24 R31.7 U3.37(SCL1/CN83/RG2) V18.1(Conn)
SPI_1_CS: J3.B10 R14.2 U6.3(1Y)
SPI_1_MISO: J3.B12 U6.12(4A)
SPI_1_MOSI: J3.B13 R12.2 U6.8(3Y)
SPI_1_SCLK: J3.B11 R13.2 U6.6(2Y)
SPI_2_MISO: J6.5 U1.2(SO) U3.14(AN2/C2INB/RP13/CN4/RB2) U7.3(1Y)
SPI_2_MOSI: J6.9 U1.5(SI) U3.12(PGED3/AN4/C1INB/RP28/CN6/RB4) U4.5(2A)
SPI_2_SCLK: J6.11 U1.6(SCK) U3.11(PGEC3/AN5/C1INA/RP18/CN7/RB5) U4.9(3A)
UART1_TTL_RX: J6.21 JP5.1 JP5.3 U3.44(RP3/CN55/PMCS2/RD10)
UART1_TTL_TX: J6.23 JP5.5 JP5.7 U3.43(RP4/CN54/RD9)
UART2_TTL_RX: J6.25 U3.46(RP11/CN49/RD0) U13.9(R_Out)
UART2_TTL_TX: J6.27 U3.45(RP12/CN56/PMCS1/RD11) U13.11(T_In)
XPORT_BOOTMODE: J6.30 MOD1.7(CP2) U3.54(C3INB/CN15/RD6)
XPORT_RESET: J6.28 MOD1.6(CP1) R3.1 U2.2(B)
XPORT_RESIN: J6.26 MOD1.3(Resin) U3.53(RP20/CN14/PMRD/RD5)
N16764009: J3.B1 U10.1(\) U11.4(IN_7_(0))
N16778169: JP1.3 U2.4(Y)
N16778254: J1.1 JP1.1
N16778356: C6.2 U3.40(OSCO/CLKO/CN22/RC15) Y1.1
N16778362: C5.2 U3.39(OSCI/CLKI/CN23/RC12) Y1.2
N16778476: C7.2 U3.47(SOSCI/C3IND/CN1/RC13) Y2.2
N16778757: R2.1 SW1.3 U2.1(A)
N16778900: C4.1 U3.56(Vcap/Vddcore)
N16779150: J1.5 U3.17(PGEC2/AN6/RP6/CN24/RB6)
N16779193: J1.4 U3.18(PGED2/AN7/RP7/CN25/RB7)
N16798610: C8.2 U3.48(SOSCO/C3INC/RPI37/CN0/RC14) Y2.1
N16812428: J3.B2 U10.2(\) U11.3(IN_6_(1))
N16812593: J3.B3 U10.3(\) U11.2(IN_5_(2))
N16812863: J3.B4 U10.4(\) U11.1(IN_4_(3))
N16813032: J3.B5 U10.5(\) U11.13(IN_3_(4))
N16813203: J3.B6 U10.6(\) U11.12(IN_2_(5))
N16813376: J3.B7 U10.7(\) U11.11(IN_1_(6))
N16813551: J3.B8 U10.8(\) U11.10(IN_0_(7))
N16835472: R26.1 U3.64(CN62/PMD4/RE4) U9.11(4Y)
N16835907: R26.3 U3.1(CN64/PMD5/RE5) U9.8(3Y)
N16836216: U3.2(SCL3/CN64/PMD6/RE6) U9.5(2A)
N16836525: U3.3(SDA3/CN65/PMD7/RE7) U9.2(1A)
N16846416: U3.30(AN15/REFO/RP29/CN12/PMA0/RB15) U5.12(4A)
N16846729: U3.29(AN14/CTPLS/RP14/CN32/PMA1/RB14) U5.9(3A)
N16847042: U3.28(TDI/PMA10/AN13/CTED1/CN31/RB13) U5.5(2A)
N16847355: U3.27(TCK/AN12/CTED2/CN30/PMA11/RB12) U5.2(1A)
N16853329: U3.34(RP30/CN70/RF2) U8.2(1A)
N16853648: U3.59(CN69/RF1) U8.5(2A)
N16853967: U3.58(CN68/RF0) U8.9(3A)
N16875579: U1.3(\\~{W}P) U3.21(AN8/RP8/CN26/RB8)
N16876348: U1.7(\\~{HOL}D) U3.22(AN9/RP9/CN27/PMA7/RB9)
N16891342: J4.1 JP4.4 JP4.6
N16891344: J4.2 JP4.2 JP4.8
N16891348: JP4.5 JP4.7 U12.8(R_In)
N16891368: JP4.1 JP4.3 U12.13(T_Out)
N16891414: C17.1 U12.2(C1+)
N16891416: C20.1 U12.5(C2+)
N16891418: C20.2 U12.6(C2-)
N16891424: C17.2 U12.4(C1-)
N16891438: C19.2 U12.7(V-)
N16891440: C18.1 U12.3(V+)
N16891552: JP5.6 U12.11(T_In)
N16891554: JP5.2 U12.9(R_Out)
N16893283: J5.1 JP6.4 JP6.6
N16893289: J5.2 JP6.2 JP6.8
N16893293: JP6.5 JP6.7 U13.8(R_In)
N16893299: JP6.1 JP6.3 U13.13(T_Out)
N16893359: C23.1 U13.2(C1+)
N16893361: C26.1 U13.5(C2+)
N16893363: C26.2 U13.6(C2-)
N16893369: C23.2 U13.4(C1-)
N16893383: C25.2 U13.7(V-)
N16893385: C24.1 U13.3(V+)
N16899863: J3.B14 MOD1.8(CP3)
N16899882: JP5.8 MOD1.5(Data_In)
N16899884: JP5.4 MOD1.4(Data_Out)
N16978416: J2.1(P1) U4.3(1Y)
N16979075: J2.2(P2) U4.6(2Y)
N16979742: J2.5(P5) U4.8(3Y)
N16980417: J2.7(P7) R7.1 U7.2(1A)
N16981444: J2.10(D) R16.1 U7.5(2A)
N16981960: J2.11(C) R17.1 U7.9(3A)
N16991910: J2.9(P9) R6.1
N16992629: J2.8(P8) R8.1
N17025280: R10.1 U4.12(4A)
N17026135: R22.1 U7.12(4A)
N17040220: U7.11(4Y) V2.1(Conn)
N17042937: U4.11(4Y) V1.1(Conn)
N17043369: U3.23(TMS/AN10/CVref/CN28/PMA13/RB10) U7.6(2Y)
N17044238: U3.24(TDO/AN11/CN29/PMA12/RB11) U7.8(3Y)
N17079626: U3.8(C2INC/RP27/CN11/PMA2/RG9) U6.2(1A)
N17080398: U3.6(C2IND/RP19/CN10/PMA3/RG8) U6.5(2A)
N17081177: U3.5(C1INC/RP26/CN9/PMA4/RG7) U6.9(3A)
N17082150: R15.2 U3.4(PMA5/RP21/C1IND/CN8/RG6) U6.11(4Y)
N17206222: R23.1 U8.12(4A)
N17209019: R25.1 U8.11(4Y) V3.1(Conn)
N17282072: JP2.10 JP2.12 R25.6
N17282723: JP2.6 JP2.8 R25.4
N17284697: JP2.14 JP2.16 R25.8
N17286022: JP2.2 JP2.4 R25.2
N17289477: JP3.10 JP3.12 R26.6
N17289479: JP3.6 JP3.8 R26.4
N17289493: JP3.14 JP3.16 R26.8
N17289499: JP3.2 JP3.4 R26.2
N17705724: U11.15(OUT_EN) V4.1(Conn)
N17710149: R11.1 U4.13(4~{OE})
N17737138: R24.1 U7.13(4~{OE})
N17780710: R9.2 U3.36(SDA1/CN84/RG3)
N17839810: D1.1(ANODE) R9.1
N18018742: JP7.10 JP7.12 R31.6
N18018748: JP7.6 JP7.8 R31.4
N18018766: JP7.14 JP7.16 R31.8
N18018780: JP7.2 JP7.4 R31.2
N18018834: JP8.10 JP8.12 R32.6
N18018840: JP8.6 JP8.8 R32.4
N18018858: JP8.14 JP8.16 R32.8
N18018868: JP8.2 JP8.4 R32.2
N18018920: JP9.10 JP9.12 R33.6
N18018926: JP9.6 JP9.8 R33.4
N18018944: JP9.14 JP9.16 R33.8
N18018958: JP9.2 JP9.4 R33.2
N18128905: D2.1(ANODE) R27.1
N18129426: D3.1(ANODE) R28.1
N18131125: D5.1(ANODE) R30.1
N18157178: D4.1(ANODE) R29.1
N18440607: J6.29 V5.1(Conn)
N18441032: J6.31 V6.1(Conn)

Not connected (* = marked no-connect by the designer): J1 6*; J2 12(W); P1 1* 2* 3* 4* 5* 6*; P4 1 2 3 4; P5 1 2 3 4; U12 1(Ready)* 10(\~{Invali}d)*; U13 1(Ready)* 10(\~{Invali}d)*

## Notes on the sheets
sheet 1
- *MCLR/Vpp
- Ground
- Vdd
- PGD
- PGC
- Not Used
- EEPROM_CS*
- SPI_2_MISO
- SD_CS*
- SPI_2_MOSI
- SPI_2_SCLK
- DIG_IN_0
- DIG_IN_1
- DIG_OUT_0
- DIG_OUT_1
- CARD_DET
- WRITE_DET
- PS_DIG_OUT_0
- DIG_ADD_GATE
- PS_DIG_OUT_1
- DIG_ADD_0
- DIG_ADD_1
- PS_DIG_OUT_2
- DIG_ADD_2
- SPI_1_MISO
- SPI_1_MOSI
- SPI_1_SCLK
- SPI_1_CS
- SD_CS*
- SPI_2_MOSI
- SPI_2_SCLK
- SD_CS*
- MOSI
- SCLK
- MISO
- SPI_2_MISO
- CARD_DET
- WRITE_DET
- CARD_DET
- WRITE_DET
sheet 2
- PS_DIG_OUT_0
- PS_DIG_OUT_1
- INT_0
- INT_1
- PS_DIG_OUT_2
- INT_2
- DIG_ADD_GATE
- INT_3
- DIG_ADD_0
- INT_4
- DIG_ADD_1
- INT_5
- DIG_ADD_2
- INT_6
- DIG_OUT_0
- DIG_OUT_1
- GND
- INT_7
- GND
- SPI_1_CS
- DIG_IN_0
- SPI1_SCK
- DIG_IN_1
- SPI1_MISO
- 3.3V_SYS
- SPI1_MOSI
- 3.3V
- GND
- 3.3V
- BUS_POWER
- Priority Interrupt
  Decoder
- 3.3V
- 3.3V
- GND
- GND
- GND
- GND
- 5.0V
- 5.0V
- GND
- GND
- 12.0V
- GND
- 12.0V
- GND
- BUS_POWER
- PIC Reset (External Reset to PIC)
  PIC Bootloader Mode (Input to PIC)
  Bus Power (On/Off to 3 Beta-Dynes)
- Place caps physically close
  to the DIN Connector
sheet 3
- Mates with FI-W31S
sheet 4
- 89mm
- J6
  Test Conn
- J4
  Main
- J5
  Debug
- J1
  PIC Prog
- 80mm
- 70mm
- XPORT
- J3
  DIN Conn
- 60mm
- 50mm
- 40mm
- J2
  SD Card Conn
- 30mm
- 20mm
- SW1
  Reset
- 10mm
- 10mm
- 20mm
- 30mm
- 40mm
- 50mm
- 60mm
- 70mm
- 80mm
- 90mm
- 100mm
- 110mm
- 120mm
- 127mm
